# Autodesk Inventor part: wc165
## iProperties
Shininess: 64.0
Length Units: 11272
Angle Units: 11279
Time Units: 11290
Mass Units: 11286
Length Display Precision: 3
Angle Display Precision: 2
Compacted: True
Part Number: wc165
Document SubType Name: Modeling
Created: 2004-08
Designer: John Blackburn
Manufacturer: Standard
Standards Organization: Custom
Material: Phenolic
Density: 0.0
Volumn: 0.0
Area: 0.0
PropertySet Name: Model Information
Control State: 0
Master: False
Checked Out: False
Author: John Blackburn
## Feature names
1. Base1
